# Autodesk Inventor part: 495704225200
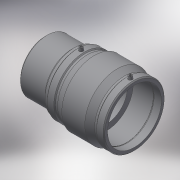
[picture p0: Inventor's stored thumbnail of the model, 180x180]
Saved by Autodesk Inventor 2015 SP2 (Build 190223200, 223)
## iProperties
Created: 2017-06
Part Number: 495704225200
Material: Generic
Description: PLASSON PE CAST IRON SPIGOT COUPLER TRANSITION 225-200
Document SubType Name: Modeling
Designer: KIM
Mass: 55.0731 g
Surface Area: 148.067 cm^2
Volume: 55.0731 cm^3
Density: 1 g/cm^3
Appearance: Default
Author: KIM
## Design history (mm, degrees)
derived "495704.ipt"
feature "Solid1::495704.ipt"
tag "TaggingFeature1"
body "Solid1"
other parameters: "d14" = 17.6296, "d15" = 118, "d16" = 118, "d17" = 213.75, "d18" = 225, "d19" = 3.52592, "d20" = 168 deg, "d22" = 255.68, "d23" = 272, "d24" = 248.0096, "d25" = 135 deg, "d26" = 96, "d27" = 135 deg, "d35" = 15, "d39" = 5 deg, "d45" = 4, "d46" = 14, "d47" = 0, "d50" = 3, "d51" = 0, "d52" = 34.22, "d53" = 8.555, "d54" = 222, "d55" = 0.1, "d56" = 244.2, "d57" = 109, "d58" = 132, "d60" = 176, "d62" = 6.66, "d65" = 11.1, "d_" = 225, "L_" = 372, "L_1" = 118, "D_1" = 272, "d_2" = 12, "L_2" = 132, "H_" = 109, "D_" = 222, "d_1" = 176
